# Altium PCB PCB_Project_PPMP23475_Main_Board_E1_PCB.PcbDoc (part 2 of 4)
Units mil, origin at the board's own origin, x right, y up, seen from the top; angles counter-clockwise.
Board outline 10826.77 x 2559.06 mil, 6 copper layers (Top Layer, Signal Layer 1, Signal Layer 2, Signal Layer 3, Signal Layer 4, Bottom Layer), stack 65.535 mil thick; 162 components, 91 nets, 425 pads, 676 vias.
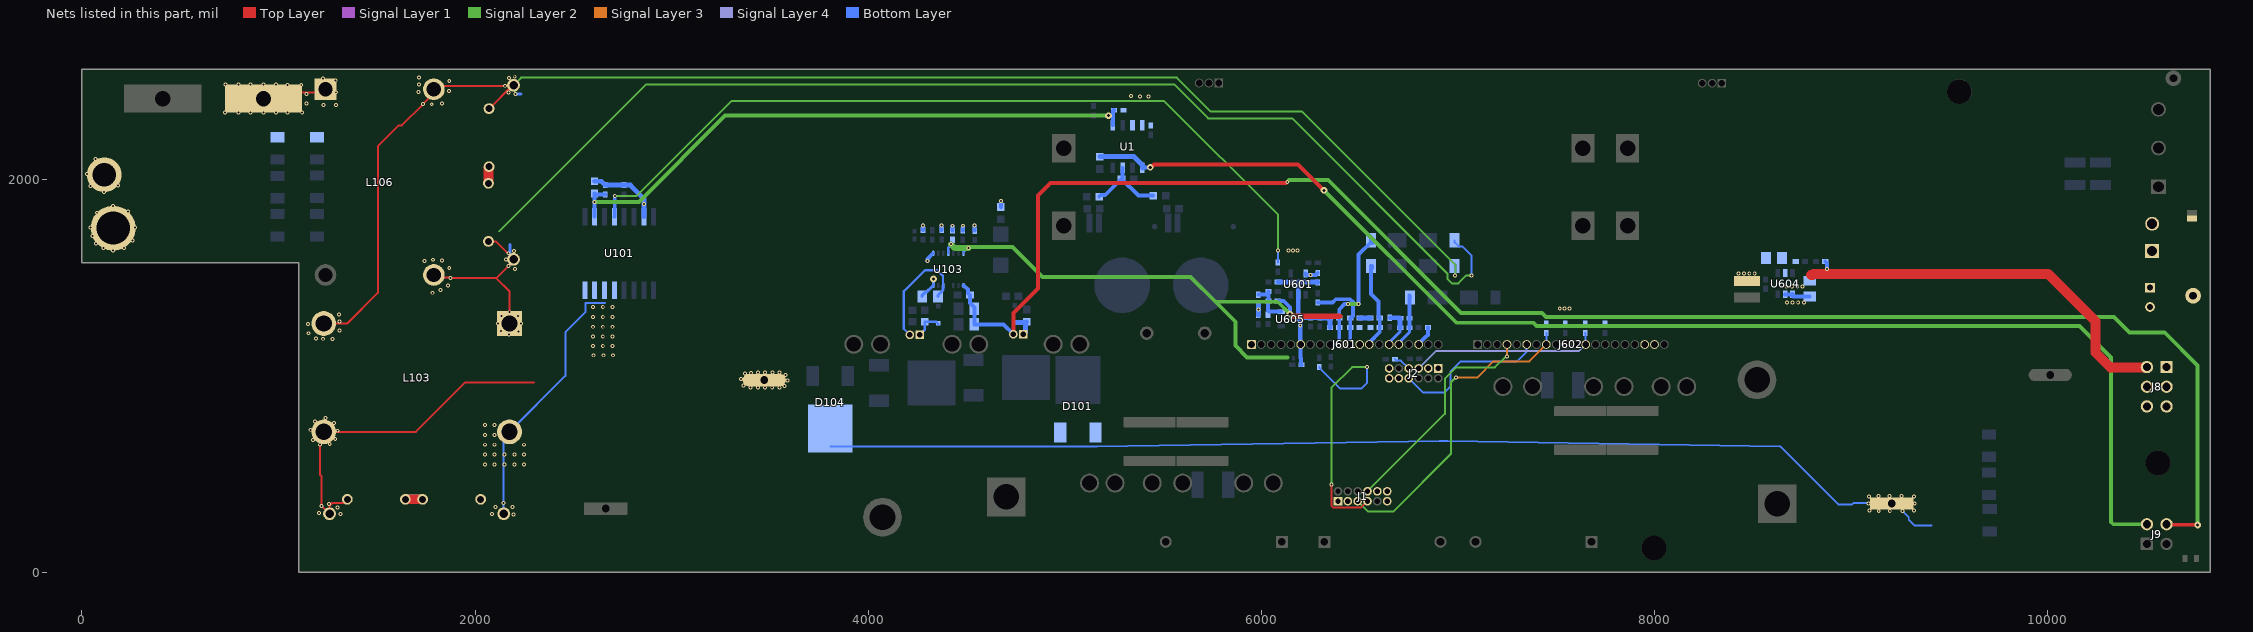
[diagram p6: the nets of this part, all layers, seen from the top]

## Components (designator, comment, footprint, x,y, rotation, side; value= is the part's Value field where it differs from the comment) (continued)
R624 "RC1206FR-071ML" 1206 9702,646 r270 bottom value=1.00Meg
R625 "CRCW040218K0FKEDC" FP-CRCW040218K0FKEDC_0402-MFG 6181,1090 r180 bottom value=18k
R626 "RC0402FR-0715KL" 0402#1 6657,1085 r180 bottom value=15.0k
R632 "CRCW04026K19FKED" 0402#1 6060,1381.49 r0 bottom value=6.19k
R637 "RC0402FR-0715KL" 0402#1 6780,1088 r180 bottom value=15.0k
R640 "RC0402FR-071KL" 0402#1 6034,1287.49 r90 bottom value=1.00k
R641 "CRCW040288K7FKED" 0402#1 8845,1582 r0 bottom value=88.7k
R642 "RC0402FR-073KL" 0402#1 5985,1286.49 r270 bottom value=3.00k
R643 "CRCW040222K1FKED" 0402#1 8742,1582 r0 bottom value=22.1k
RT1 "B59451C1130B070" S237 5564.64,1218 r180 top value=56
SW_PH1_1 "0312-0-15-15-34-27-10-0" Mill-Max_0312-0-15-15-34-27-10-0 5126,455 r90 top
SW_PH1_2 "0312-0-15-15-34-27-10-0" Mill-Max_0312-0-15-15-34-27-10-0 5256,455 r90 top
SW_PH2_1 "0312-0-15-15-34-27-10-0" Mill-Max_0312-0-15-15-34-27-10-0 8034,946 r270 top
SW_PH2_2 "0312-0-15-15-34-27-10-0" Mill-Max_0312-0-15-15-34-27-10-0 8164,946 r270 top
TP101 "Vo" Keystone5000 10640,2514 r180 top value=Red
TP103 "PGND_PFC" Keystone5001 10740,1408 r180 top value=Black
U1 "UCC5350SBDR" D0008B_HV 5320,2167 r270 bottom
U101 "ACS724KMATR-50AB-T" SOIC-16 2734,1623 r90 bottom
U103 "UCC21225ANPL" NPL0013A 4408,1542.38 r270 bottom
U601 "OPA376AIDBVR" DBV0005A_N 6188,1467.49 r90 bottom
U604 "TPS560430XDBVR" DBV0006A_N 8665,1469 r270 bottom
U605 "TLV431AIDBZR" DBZ0003A_N 6148,1289.49 r0 bottom
VB_LF_1 "0312-0-15-15-34-27-10-0" Mill-Max_0312-0-15-15-34-27-10-0 4941,1161 r270 top
VB_LF_2 "0312-0-15-15-34-27-10-0" Mill-Max_0312-0-15-15-34-27-10-0 5077,1161 r270 top
VB_PH1_1 "0312-0-15-15-34-27-10-0" Mill-Max_0312-0-15-15-34-27-10-0 5910,455 r90 top
VB_PH1_2 "0312-0-15-15-34-27-10-0" Mill-Max_0312-0-15-15-34-27-10-0 6061,455 r90 top
VB_PH2_1 "0312-0-15-15-34-27-10-0" Mill-Max_0312-0-15-15-34-27-10-0 7229,946 r270 top
VB_PH2_2 "0312-0-15-15-34-27-10-0" Mill-Max_0312-0-15-15-34-27-10-0 7380,946 r270 top

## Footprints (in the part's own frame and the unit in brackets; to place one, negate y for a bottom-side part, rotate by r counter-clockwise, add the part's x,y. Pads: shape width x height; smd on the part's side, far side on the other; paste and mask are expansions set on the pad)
0402#1 [mm] "0402 from SM-752 data"
  rect 0.8x0.6 smd: 1(-0.6,0) 2(0.6,0)
  silkscreen extent -1.22,-0.52 1.22,0.52, body extent -0.55,-0.3 0.55,0.3, height 0.6
0402#2 [mm] "Chip Capacitor, Body 1.0x0.5mm, IPC High Density"
  rect 0.6x0.5 smd: 1(-0.5,0) 2(0.5,0)
  body extent -0.55,-0.3 0.55,0.3, height 1.3
0603 [mm] "0603 from SM-752 data"
  rect 1x0.95 smd: 1(-0.8,0) 2(0.8,0)
  silkscreen extent -1.52,-0.69 1.52,0.69, body extent -0.87,-0.47 0.87,0.47, height 1
0805_HV [mil] "0805 with 30mil clearance between pads"
  rect 50x63 smd: 1(-40,0) 2(40,0)
  silkscreen extent -74,-40 74,40, body extent -43,-29 43,29, height 57
1206 [mm] "1206 from SM-752 data"
  rect 1.3x1.85 smd: 1(-1.45,0) 2(1.45,0)
  silkscreen extent -2.4,-1.21 2.4,1.21, body extent -1.7,-0.9 1.7,0.9, height 1.35
1210_220 [mm] "1210"
  rect 1.3x2.7 smd: 1(-1.45,0) 2(1.45,0)
  silkscreen extent -2.32,-1.57 2.32,1.57, body extent -1.7,-1.35 1.7,1.35, height 2.2
1812_254 [mm] "SMD, 2-Leads, Body 4.8x3.4mm"
  rect 1.6x3.4 smd: 1(-2,0) 2(2,0)
  silkscreen extent -0.8,-1.7 0.8,1.7, body extent -2.4,-1.7 2.4,1.7, height 2.54
CAPPR250W50D630H1120 [mm] "PANASONIC"
  rect 1.25x1.25 hole 0.75: 1(-1.25,0)
  round 1.25 hole 0.75: 2(1.25,0)
  silkscreen extent -3.4,-3.4 3.4,3.4, body extent -3.37,-3.39 3.4,3.39, height 12.21
D0008B_HV [mm] "SOIC, 8-Leads, Body 4.9x3.9mm, Pitch 1.27mm, HV / Isolation option"
  rrect17% 1.4x0.6 smd: 1(-2.75,1.905) 2(-2.75,0.635) 3(-2.75,-0.635) 4(-2.75,-1.905) 5(2.75,-1.905) 6(2.75,-0.635) 7(2.75,0.635) 8(2.75,1.905)
  silkscreen extent -3.3,-2.5 0.9,2.5, body extent -3,-2.45 3,2.45, height 1.63
DBV0005A_N [mm] "SOT23, 5-Leads, Body 2.9x1.6mm, Pitch 0.95mm, Lead Span 2.8mm, IPC Medium Density"
  rrect17% 1x0.6 smd: 1(-1.375,0.95) 2(-1.375,0) 3(-1.375,-0.95) 4(1.375,-0.95) 5(1.375,0.95)
  silkscreen extent -0.25,-1.55 0.25,1.55, body extent -1.42,-1.46 1.42,1.46, height 1.09
DBV0006A_N [mm] "SOT23, 6-Leads, Body 2.9x1.6mm, Pitch 0.95mm, Lead Span 2.8mm, IPC Medium Density"
  rrect17% 1x0.6 smd: 1(-1.375,0.95) 2(-1.375,0) 3(-1.375,-0.95) 4(1.375,-0.95) 5(1.375,0) 6(1.375,0.95)
  silkscreen extent -1.68,-1.55 0.5,1.55, body extent -1.42,-1.46 1.42,1.46, height 1.12
DBZ0003A_N [mm] "SOT23, 3-Leads, Body 2.9x1.3mm, Pitch 0.95mm, Lead Span 2.4mm, IPC Medium Density"
  rrect17% 1x0.6 smd: 1(-1.2,0.95) 2(-1.2,-0.95) 3(1.2,0)
  silkscreen extent 0.2,-1.5 0.7,1.5, body extent -1.26,-1.46 1.26,1.46, height 0.98
DPAK [mm] "D-PAK, 3-Pads, Body 6.22x6.73mm (max), TO-252AA using nominal STEP model"
  rrect6% 2.6x1.6 smd: 1(-3.4,2.28) 3(-3.4,-2.28)
  rrect2% 6.2x5.8 smd paste-3: 2(3.4,0)
  body extent -3.86,-3.29 5.84,3.29, height 2.48
FCC_disclaimer [mil]
FP-86H-22021C_PTH_IND_30MM0_14MM2-MFG [mm]
  rrect2% 5x5 hole 3.3 paste-2539.97 mask+0: 1(-8,-1.3)
  round 5 hole 3.3 paste-2539.97 mask+0: 2(8,1.3)
  silkscreen extent -15,-7.1 15,7.1, body extent -15.1,-7.2 15.1,7.2, height 0.25
FP-ARCDC302030E282N2B_PTH_30MM0_20MM0-MFG [mm]
  rrect3% 3.2x3.2 hole 2.1 paste-2539.97 mask+0: 1(7,-12)
  round 3.2 hole 2.1 paste-2539.97 mask+0: 2(7,12) 3(-7,12) 4(-7,-12)
  silkscreen extent -10,-15 10.72,15, body extent -10.1,-15.1 10.1,15.1, height 0.25
FP-C2225C154KDRAC7800_2225-MFG [mm]
  rrect8% 1.3x6.7 smd paste+0 mask+0: 1(-2.5,0) 2(2.5,0)
  silkscreen extent -1.48,-3.4 1.48,3.4, body extent -3.25,-3.5 3.25,3.5, height 0.25
FP-CRCW040218K0FKEDC_0402-MFG [mm]
  rrect25% 0.4x0.6 smd paste+0 mask+0: 1(-0.45,0) 2(0.45,0)
  silkscreen extent -0.55,-0.67 0.55,0.67, body extent -0.5,-0.25 0.5,0.25, height 0.35
FP-ERJ-H3G0R00V_0603-MFG [mm]
  rrect15% 0.65x0.9 smd paste+0 mask+0: 1(-0.725,0) 2(0.725,0)
  silkscreen extent 0,-0.48 0,0.48, body extent -1.15,-0.58 1.15,0.58, height 0.25
FP-IPT60R080G7XTMA1_HSOF-8-MFG [mm]
  rrect13% 0.8x2.5 smd paste-1000 mask+0: 1(-4.2,-5.35) 2(-3,-5.35)
  round 0.709 smd paste-1000 mask+0: 3-4-5-6-7-8(4.206,-4.881)
  round 7.2 smd paste-1000 mask+0: 9(0,2.7)
  Top Layer region: -2.2,-4.1 4.6,-4.1 4.6,-6.6 3.8,-6.6 3.8,-4.6 3.4,-4.6 3.4,-6.6 2.6,-6.6 2.6,-4.6 2.2,-4.6 2.2,-6.6 1.4,-6.6 1.4,-4.6 1,-4.6 1,-6.6 0.2,-6.6 0.2,-4.6 -0.2,-4.6 -0.2,-6.6 -1,-6.6 -1,-4.6 -1.4,-4.6 -1.4,-6.6 -2.2,-6.6 -2.2,-4.1
  Top Layer region: -4.85,-1.3 4.85,-1.3 4.85,2.4 4.35,2.4 4.35,5.2 5.05,5.2 5.05,6.7 -5.05,6.7 -5.05,5.2 -4.35,5.2 -4.35,2.4 -4.85,2.4
  body extent -4.95,-5.79 4.95,5.89, height 2.31
FP-M50-3000645_HDR12-MFG [mm]
  rrect9% 1.12x1.12 hole 0.7 paste-2539.97 mask+0: 1(-3.175,-0.635)
  round 1.12 hole 0.7 paste-2539.97 mask+0: 2(-3.175,0.635) 3(-1.905,-0.635) 4(-1.905,0.635) 5(-0.635,-0.635) 6(-0.635,0.635) 7(0.635,-0.635) 8(0.635,0.635) 9(1.905,-0.635) 10(1.905,0.635) 11(3.175,-0.635) 12(3.175,0.635)
  silkscreen extent -4.73,-1.63 4.16,1.63, body extent -4.26,-1.73 4.26,1.73, height 0.25
FP-M50-3030242_HDR2-MFG [mm]
  rrect9% 1.12x1.12 hole 0.7 paste-2539.97 mask+0: 1(-0.635,0)
  round 1.12 hole 0.7 paste-2539.97 mask+0: 2(0.635,0)
  silkscreen extent -2.25,-0.97 1.62,0.97, body extent -1.72,-1.07 1.72,1.07, height 0.25
FP-M52-040023V0345_HDR3-MFG [mm]
  rrect9% 1.12x1.12 hole 0.85 paste-2539.97 mask+0: 1(-1.27,0)
  round 1.12 hole 0.85 paste-2539.97 mask+0: 2(0,0) 3(1.27,0)
  silkscreen extent -2.15,-1.97 2.15,1.37, body extent -1.91,-1.25 1.91,1.25, height 6.84
FP-M52-040023V2045_HDR20-MFG [mm]
  rrect9% 1.12x1.12 hole 0.85 paste-2539.97 mask+0: 1(-12.065,0)
  round 1.12 hole 0.85 paste-2539.97 mask+0: 2(-10.795,0) 3(-9.525,0) 4(-8.255,0) 5(-6.985,0) 6(-5.715,0) 7(-4.445,0) 8(-3.175,0) 9(-1.905,0) 10(-0.635,0) 11(0.635,0) 12(1.905,0) 13(3.175,0) 14(4.445,0) 15(5.715,0) 16(6.985,0) 17(8.255,0) 18(9.525,0) 19(10.795,0) 20(12.065,0)
  silkscreen extent -12.95,-1.97 12.95,1.37, body extent -12.7,-1.25 12.7,1.25, height 6.84
FP-PAL6493.144NL_PTH_IND_36MM0_33MM0-MFG [mm]
  rrect6% 5.6x1.6 hole 1 slot 5 at 0 deg paste-2539.97 mask+0: 1(10.25,8.3)
  rrect100% 5.6x1.6 hole 1 slot 5 at 0 deg paste-2539.97 mask+0: 2(-10.25,-8.3)
  silkscreen extent -18,-16.5 18.62,16.5, body extent -18.1,-16.6 18.1,16.6, height 0.25
FP-R523I347050P3K_RADIAL-MFG [mm]
  rrect6% 1.55x1.55 hole 1 paste-2539.97 mask+0: 1(-7.5,0)
  round 1.55 hole 1 paste-2539.97 mask+0: 2(7.5,0)
  silkscreen extent -9.15,-3.85 9.15,3.85, body extent -9.25,-3.95 9.25,3.95, height 0.25
FP-SSW-102-02-G-D_HDR4-MFG [mm]
  rrect6% 1.59x1.59 hole 1.04 paste-2539.97 mask+0: 1(1.27,-1.27)
  round 1.59 hole 1.04 paste-2539.97 mask+0: 2(1.27,1.27) 3(-1.27,-1.27) 4(-1.27,1.27)
  silkscreen extent -2.92,-2.54 3.65,2.54, body extent -3.02,-2.64 3.02,2.64, height 0.25
FP-SSW-103-02-G-D_RCPT6-MFG [mm]
  rrect6% 1.59x1.59 hole 1.04 paste-2539.97 mask+0: 1(2.54,-1.27)
  round 1.59 hole 1.04 paste-2539.97 mask+0: 2(2.54,1.27) 3(0,-1.27) 4(0,1.27) 5(-2.54,-1.27) 6(-2.54,1.27)
  silkscreen extent -4.19,-3.12 4.19,2.54, body extent -4.29,-2.64 4.29,2.64, height 0.25
FP-YXS80660T_PTH_30MM0_19MM0-MFG [mm]
  rrect4% 2.8x2.8 hole 1.85 paste-2539.97 mask+0: 1(-12,-7)
  round 2.8 hole 1.85 paste-2539.97 mask+0: 2(12,-7) 3(12,7) 4(-12,7)
  silkscreen extent -15.72,-9.5 15,9.5, body extent -15.1,-9.6 15.1,9.6, height 0.25
IEC_HighVoltage_Small [mil]
  silkscreen extent -107,-88 107,97
IEC_HotSurface_Small [mil]
  silkscreen extent -107,-93 107,92
Keystone5000 [mil] "For Keystone 500x miniature loop terminals"
  round 80 hole 40: 1(0,0)
  silkscreen extent -52,-52 52,52, body extent -49,-49 49,49, height 182
Keystone5001 [mil] "For Keystone 500x miniature loop terminals"
  round 80 hole 40: 1(0,0)
  silkscreen extent -52,-52 52,52, body extent -49,-49 49,49, height 182
Mill-Max_0312-0-15-15-34-27-10-0 [mm] "Pin Receptacle, .032-.046\" .075\" Dia, Gold, TH"
  round 2.45 hole 1.905: 1(0,0)
  silkscreen extent -1.52,-1.52 1.52,1.52, body extent -1.15,-1.15 1.16,1.15, height 0.46
Net-Tie_50milWide_30milLong [mil] "50mil net tie, no solder mask opening, no solder paste"
  rect 30x50 smd paste-20 mask-20: 1(-15,0) 2(15,0)
NPL0013A [mm] "SMD, 13-Leads, Body 5x5mm, Pitch 0.65mm"
  rrect33% 0.65x0.3 smd: 1(-2.075,1.95) 2(-2.075,1.3) 3(-2.075,0.65) 4(-2.075,0) 5(-2.075,-0.65) 6(-2.075,-1.3) 7(-2.075,-1.95) 8(2.075,-1.95) 9(2.075,-1.3) 10(2.075,-0.65) 11(2.075,0.65) 12(2.075,1.3) 13(2.075,1.95)
  silkscreen extent -2.5,-2.65 2.5,2.65, body extent -2.5,-2.5 2.5,2.5, height 0.91
S237 [mm] "EPCOS"
  round 1.75 hole 1.1: 1(-3.75,0) 2(3.75,0)
  silkscreen extent -7.5,-3.5 7.5,3.5, body extent -7.47,-3.5 7.47,3.5, height 21.99
SMA [mm] "Molded Diode, 2-Leads, Body 4.3x2.6mm, IPC Medium Density, based on OnSemi component dimensions and land pattern"
  rect 2x2 smd: 1(-2,0) 2(2,0)
  silkscreen extent -3.66,-1.57 2.79,1.57, body extent -2.6,-1.3 2.6,1.3, height 2.42
SOD-323 [mm] "NXP recommended land pattern"
  rect 0.6x0.6 smd paste-0.05: 1(-1.1,0) 2(1.1,0)
  silkscreen extent -2.06,-0.86 1.53,0.86, body extent -1.3,-0.67 1.3,0.68, height 1.1
SOIC-16 [mm] "SOIC, 16-Leads, Body 10.3x7.5mm, Pitch 1.27mm"
  rrect15% 2.25x0.65 smd: 1(-4.75,4.445) 2(-4.75,3.175) 3(-4.75,1.905) 4(-4.75,0.635) 5(-4.75,-0.635) 6(-4.75,-1.905) 7(-4.75,-3.175) 8(-4.75,-4.445) 9(4.75,-4.445) 10(4.75,-3.175) 11(4.75,-1.905) 12(4.75,-0.635) 13(4.75,0.635) 14(4.75,1.905) 15(4.75,3.175) 16(4.75,4.445)
  silkscreen extent -4.87,-5.25 3.8,5.45, body extent -5.32,-5.25 5.32,5.25, height 2.64
TE_282856-3 [mm] "Receptacle, 3x1, 5mm, R/A, TH"
  rect 1.9x1.9 hole 1.4: 1(-5,0)
  round 1.9 hole 1.4: 2(0,0) 3(5,0)
  silkscreen extent -8,-5 8,5, body extent -7.5,-5 8,5, height 19
WCAP-FTXX_L26W15H25 [mm] "Film Capacitors, 26x15x25mm"
  round 1.65 hole 1.1: 1(-11.25,0) 2(11.25,0)
  silkscreen extent -13.25,-7.75 13.25,7.75, body extent -13,-7.5 13,7.5, height 30.05
WE-MAPI_3020 [mm] "SMD, 2-Leads, Body 3.2x3.2mm"
  rect 1.3x3.4 smd: 1(-1.05,0) 2(1.05,0)
  silkscreen extent -0.1,-1.6 0.1,1.6, body extent -1.6,-1.6 1.6,1.6, height 2
WEEE_Minimum [mil] "WEEElie bin"
  silkscreen extent -95,-172 99,104
Wurth_691214110002 [mm] "Receptacle, 3.5mm, 2x1, TH"
  rect 1.8x1.8 hole 1.3: 1(-1.75,0)
  round 1.8 hole 1.3: 2(1.75,0)
  silkscreen extent -3.8,-3.4 3.5,4, body extent -3.9,-3.4 3.5,4, height 8.5
Y_CAP [mm]
  round 1.4 hole 0.9: 1(-0.165,3.701) 2(-0.165,-3.799)
  silkscreen extent 0.08,-3.7 7.72,3.67, body extent -0.47,-4.1 7.73,4, height 5

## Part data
C1: library part CMP-0007150-5, "CAP, CERM, 1 uF, 35 V, +/- 10%, X5R, 0603", Cap_Case=0603, Manufacturer="Taiyo Yuden", Supplier Part Number 1=587-1437-1-ND, TempCo=X5R, Tolerance_%=10%, Value1=Unknown, Value2=35V, ValueDisplayed=1uF
C2 C3 C4 C5: library part CMP-0097403-1, "Cap Ceramic 0.15uF 1000V X7R 10% SMD 2225 125°C Embossed Plastic T/R", Digikey Part Number=399-C2225C154KDRAC7800CT-ND, Manufacturer=KEMET, Mouser Part Number=80-C2225C154KDR, Operating Temperature Range="-55°C to +125°C", TempCo=15%, Temperature Characteristic=X7R, Tolerance_%=10%, ValueDisplayed=0.15uF
C101 C102: "CAP, CERM, 0.047 µF, 630 V, +/- 10%, X7R, 1210", Cap_Case=1210, Manufacturer=MuRata, Supplier Part Number 1=490-3516-1-ND, TempCo=X7R, Tolerance_%=10, Value1=Unknown, Value2=630V, ValueDisplayed=0.047µF
C104 C105 C111 C112: library part CMP-0009609-4, "CAP, CERM, 1000 pF, X1 400 VAC/Y2 440 VAC, +/- 20%, E, TH", Cap_Case=7x5x10mm, Manufacturer=MuRata, Supplier Part Number 1="490-16237-1-ND - Cut Tape", TempCo=E, Tolerance_%=20%, Value1=Unknown, ValueDisplayed=1000pF
C106 C110 C124: library part CMP-0092709-1, "Cap Film 0.47uF 630V PP 10% Dipped 15mm 110°C Bulk", Digikey Part Number=399-R523I347050P3K-ND, Manufacturer=KEMET, Mouser Part Number=80-R523I347050P3K, Operating Temperature Range="-40°C to +110°C", Tolerance_%=10%, ValueDisplayed=0.47uF, Voltage Ac Rating X=310V
C108 C109: library part 890334026034, "WCAP-FTXX Film Capacitor, THT, L26W15H25, 2.2uF, 310V", Capacitance Tolerance=+/-10%, Insulation Resistance="10000Ohm x F", Manufacturer="Wurth Elektronik", Operating Temperature="-40 to +105degC", Rated Voltage=310VAC, Rate of Voltage Rise=170V/us
C113 C120 C623: library part CMP-0860555-1, "CAP, CERM, 0.1 µF, 25 V,+/- 10%, X7R, 0402", Cap_Case=0402, Manufacturer=Yageo, TempCo=X7R, Tolerance_%=10%, Value2=25V, ValueDisplayed=0.1µF
C114: "CAP, CERM, 1uF, 6.3V, +/-10%, X5R, 0603", Cap_Case=0603, Manufacturer=MuRata, Supplier Part Number 1=81-GRM185R60J105KE26, TempCo=X5R, Tolerance_%=10, Value1=Unknown, Value2=6.3V, ValueDisplayed=1µF
C115: "CAP, CERM, 1000pF, 6.3V, +/-10%, X5R, 0402", Cap_Case=0402, Manufacturer=MuRata, Supplier Part Number 1=GRM155R60J102KA01D-ND, TempCo=X5R, Tolerance_%=10, Value1=Unknown, Value2=6.3V, ValueDisplayed=1000pF
C116 C118 C126: library part CMP-0007827-2, "CAP, CERM, 22 uF, 16 V, +/- 20%, X5R, 0805", Cap_Case=0805, Manufacturer=TDK, Supplier Part Number 1=445-7647-1-ND, TempCo=X5R, Tolerance_%=20%, Value1=Unknown, Value2=16V, ValueDisplayed=22uF
C117: library part CMP-0081457-1, "CAP, CERM, 1 µF, 10 V,+/- 20%, X5R, 0402", Cap_Case=0402, Manufacturer="Yageo America", TempCo=X5R, Tolerance_%=20%, Value2=10V, ValueDisplayed=1µF
C119: "CAP, CERM, 1uF, 25V, +/-10%, X7R, 0603", Cap_Case=0603, Manufacturer=TDK, Supplier Part Number 1=445-5956-1-ND, TempCo=X7R, Tolerance_%=10, Value1=Unknown, Value2=25V, ValueDisplayed=1uF
C122 C123 C128: library part CMP-0006235-2, "CAP, CERM, 1000 pF, 50 V, +/- 10%, X7R, 0402", Cap_Case=0402, Manufacturer=Kemet, Supplier Part Number 1=399-1032-1-ND, TempCo=X7R, Tolerance_%=10%, Value1=Unknown, Value2=50V, ValueDisplayed=1000pF
C127: library part CMP-0860557-1, "CAP, CERM, 4700 pF, 25 V,+/- 10%, X7R, 0402", Cap_Case=0402, Manufacturer=Yageo, TempCo=X7R, Tolerance_%=10%, Value2=25V, ValueDisplayed=4700pF
C130 C131: library part CMP-0009326-2, "CAP, CERM, 0.1 uF, 1000 V, +/- 10%, X7R, 1812", Cap_Case=1812, Manufacturer=Kemet, Supplier Part Number 1=399-6523-1-ND, TempCo=X7R, Tolerance_%=10%, Value1=Unknown, Value2=1000V, ValueDisplayed=0.1uF
C601: "CAP, CERM, 0.1uF, 6.3V, +/-10%, X7R, 0402", Cap_Case=0402, Manufacturer=MuRata, Supplier Part Number 1=GRM155R70J104KA01D-ND, TempCo=X7R, Tolerance_%=10, Value1=Unknown, Value2=6.3V, ValueDisplayed=0.1uF
C603 C608 C610 C613 C615: library part CMP-0006266-2, "CAP, CERM, 0.047 uF, 10 V, +/- 10%, X5R, 0402", Cap_Case=0402, Manufacturer=TDK, Supplier Part Number 1=445-4980-1-ND, TempCo=X5R, Tolerance_%=10%, Value1=Unknown, Value2=10V, ValueDisplayed=0.047uF
C604 C605 C606 C624: library part CMP-0860558-1, "CAP, CERM, 220 pF, 50 V,+/- 10%, X7R, 0402", Cap_Case=0402, Manufacturer=Yageo, TempCo=X7R, Tolerance_%=10%, Value2=50V, ValueDisplayed=220pF
C609 C612 C614 C616: library part CMP-0006215-2, "CAP, CERM, 10 pF, 50 V, +/- 5%, C0G/NP0, 0402", Cap_Case=0402, Manufacturer="Wurth Elektronik", Supplier Part Number 1=732-7469-1-ND, TempCo=C0G/NP0, Tolerance_%=5%, Value1=Unknown, Value2=50V, ValueDisplayed=10pF
C619: library part CMP-0010333-1, "CAP, AL, 100 uF, 25 V, +/- 20%, TH", Cap_Case="Radial 6.3x11.2", Manufacturer=Panasonic, Supplier Part Number 1=P13476-ND, Tolerance_%=20%, Value1=Unknown, Value2=25V, ValueDisplayed=100uF
C620: library part CMP-0007870-2, "CAP, CERM, 4.7 uF, 25 V, +/- 10%, X7R, 0805", Cap_Case=0805, Manufacturer=TDK, Supplier Part Number 1=445-5972-1-ND, TempCo=X7R, Tolerance_%=10%, Value1=Unknown, Value2=25V, ValueDisplayed=4.7uF
C621: library part CMP-0007989-2, "CAP, CERM, 22 uF, 6.3 V, +/- 10%, X5R, 0805", Cap_Case=0805, Manufacturer="Samsung Electro-Mechanics", TempCo=X5R, Tolerance_%=10%, Value1=Unknown, Value2=6.3V, ValueDisplayed=22uF
C622: library part CMP-0081010-1, "CAP, CERM, 2.2 µF, 25 V,+/- 20%, X5R, 0402", Cap_Case=0402, Manufacturer=MuRata, Supplier Part Number 1=490-10457-1-ND, TempCo=X5R, Tolerance_%=20%, Value2=25V, ValueDisplayed=2.2µF
D101 D102 D104 D105: library part CMP-0077041-3, "Diode, Ultrafast, 600 V, 15 A, DPAK", Manufacturer=VISHAY, Value1=15A, Value2=1.15V
D103 D106: library part CMP-0028458-2, "Diode, Schottky, 30 V, 0.2 A, SOD-323", Manufacturer="Diodes Inc.", Value1=0.2A, Value2=0.7V
D107: "Diode, Ultrafast, 600V, 1A, SMA", Manufacturer="ON Semiconductor", Supplier Part Number 1=MURA160T3GOSCT-ND, Value1=1A, Value2=1.05V
J1 J2: library part CMP-0094055-1, "12 Position Receptacle Connector 0.050\" (1.27mm) Through Hole Gold", Current_A=1A, Digikey Part Number=952-1366-5-ND, Manufacturer=Harwin, Mouser Part Number=855-M50-3000645, Operating Temperature Range="-40°C to +105°C"
J01 J3: library part CMP-0097093-1, "Connector Header Through Hole 3 position 0.050\" (1.27mm)", Current_A=1A, Digikey Part Number=952-3508-ND, Manufacturer=Harwin, Mouser Part Number=855-M52-040023V0345, Operating Temperature Range="-40°C to +105°C"
J6 J7: library part CMP-0097274-1, "2 Position Receptacle Connector 0.050\" (1.27mm) Through Hole Gold", Current_A=1A, Digikey Part Number=952-3574-ND, Manufacturer=Harwin, Mouser Part Number=855-M50-3030242, Operating Temperature Range="-40°C to +105°C"
J8: library part CMP-0090625-1, "6 Position Receptacle Connector  Through Hole", Current_A=4.7A, Digikey Part Number=SAM1214-03-ND, Manufacturer=SAMTEC, Mouser Part Number=200-SSW10302GD, Operating Temperature Range="-55°C to +125°C", Voltage_V=655V
J9: library part CMP-0090624-1, "Board-To-Board Connector, Dual, SSW Series, 4 Contacts, Receptacle, 2.54 mm, Through Hole, 2 Rows", Current_A=4.7A, Digikey Part Number=SAM1214-02-ND, Manufacturer=Samtec, Mouser Part Number=200-SSW10202GD, Operating Temperature Range="-55°C to +125°C", Voltage_V=655V
J101: "Receptacle, 3x1, 5mm, R/A, TH", Color=Green, Current_A=24, Manufacturer="TE Connectivity", Supplier Part Number 1=A98356-ND, Voltage_V=300
J601 J602: library part CMP-0097094-1, "Connector Header Through Hole 20 position 0.050\" (1.27mm)", Current_A=1A, Digikey Part Number=952-3513-ND, Manufacturer=Harwin, Mouser Part Number=855-M52-040023V2045, Operating Temperature Range="-40°C to +105°C"
J604: library part CMP-0054825-2, "Terminal Block, 3.5mm, 2x1, Tin, TH", Color=Green, Current_A=10A, Manufacturer="Wurth Elektronik", Supplier Part Number 1=732-2747-ND, Voltage_V=300V
L1 L2: library part CMP-0096870-1, "Inductor, Buck/Boost, EDY35, TH", Manufacturer=Pulse, Operating Temperature Range="-40°C to +125°C", Test Frequency=100kHz, Tolerance_%=10%
L102 L104: library part CMP-0097059-1, "Inductor 16.2uH 12mOhm 30x14.2x33.3 TH", Manufacturer="Delta Electronics", Operating Temperature Range=to, Test Frequency=200kHz
L103: library part CMP-0097286-1, "Common Mode Choke 2.8mH 3.8mΩ", Manufacturer=Sunlord, Operating Temperature Range="-40°C to +105°C", Test Frequency=10kHz, Tolerance_%=25%
L106: library part CMP-0097287-1, "COMMON MODE CHOKE 1mH @ 10kHz 2.4mohm 1000VAC", Manufacturer="Yaxin Electronics", Operating Temperature Range=to, Test Frequency=10kHz
L601: library part CMP-0064157-1, "Inductor, Shielded, 10 uH, 1.2 A, 0.322 ohm, SMD", Manufacturer="Wurth Elektronik", Supplier Part Number 1=732-5700-1-ND, Value1="0.322 ohm", Value2=1.2A, ValueDisplayed=10uH
LOGO601: library part CMP-0074837-1, "IEC 61010-1 Hot Surface Warning"
LOGO602: library part CMP-0074835-1, "IEC 61010-1 High Voltage Warning"
Logo603: library part CMP-0074847-1, "FCC_disclaimer"
Logo604: library part CMP-0074769-1
N_LF_1 N_LF_2 PGND_LF_1 PGND_LF_2 PGND_PH1_1 PGND_PH1_2 PGND_PH2_1 PGND_PH2_2 SW_PH1_1 SW_PH1_2 SW_PH2_1 SW_PH2_2 VB_LF_1 VB_LF_2 VB_PH1_1 VB_PH1_2 VB_PH2_1 VB_PH2_2: library part CMP-0055026-1, "Pin Receptacle, .032-.046\" .075\" Dia, Gold, TH", Manufacturer=Mill-Max, Supplier Part Number 1=0312-015153427100-ND
NT1: library part CMP-0078142-6, "Single point connection between nets.", Manufacturer=N/A
Q101 Q106: library part CMP-0086487-1, "MOSFET N-CH 650V 23A HSOF-8", Manufacturer=Infineon
R1: library part CMP-0097467-1, "0 Ohms Jumper 0.125W, 1/8W Chip Resistor 0603 (1608 Metric) Automotive AEC-Q200 Thick Film", Digikey Part Number=10-ERJ-H3G0R00VCT-ND, Manufacturer=Panasonic, Mouser Part Number=667-ERJ-H3G0R00V, Operating Temperature Range="-55°C to +175°C", Power_W=125mW
R101 R104: library part CMP-0022900-4, "RES, 1.00, 1%, 0.1 W, 0603", Manufacturer=Yageo, Power_W=100mW, Supplier Part Number 1=311-1.00HRCT-ND, TempCo="200 ppm/C", Tolerance_%=1%, Value2=0.1W, Value_Code=1R00, ValueDisplayed=1.00
R102 R111: library part CMP-0022751-4, "RES, 10.0, 1%, 0.1 W, 0603", Manufacturer=Yageo, Power_W=100mW, Supplier Part Number 1=311-10.0HRCT-ND, TempCo="100 ppm/C", Tolerance_%=1%, Value2=0.1W, Value_Code=10R0, ValueDisplayed=10.0
R103 R106: library part CMP-0022746-5, "RES, 10.0 k, 1%, 0.1 W, 0603", Manufacturer=Yageo, Power_W=100mW, Supplier Part Number 1=311-10.0KHRCT-ND, TempCo="100 ppm/C", Tolerance_%=1%, Value2=0.1W, Value_Code=10k0, ValueDisplayed=10.0k
R105 R114: library part CMP-0022895-5, "RES, 1.00 k, 1%, 0.1 W, 0603", Manufacturer=Yageo, Power_W=100mW, Supplier Part Number 1=311-1.00KHRCT-ND, TempCo="100 ppm/C", Tolerance_%=1%, Value2=0.1W, Value_Code=1k00, ValueDisplayed=1.00k
R107 R108 R109 R110 R112 R113: library part CMP-0017836-2, "RES, 100 k, 1%, 0.25 W, 1206", Manufacturer="Yageo America", Power_W=250mW, Supplier Part Number 1=311-100KFRCT-ND, TempCo="100 ppm/C", Tolerance_%=1%, Value2=0.25W, Value_Code=100k
R117: library part CMP-0022908-4, "RES, 20.0, 1%, 0.1 W, 0603", Manufacturer=Yageo, Power_W=100mW, Supplier Part Number 1=311-20.0HRCT-ND, TempCo="100 ppm/C", Tolerance_%=1%, Value2=0.1W, Value_Code=20R0, ValueDisplayed=20.0
R118 R120 R122: "RES, 1.0k ohm, 5%, 0.063W, 0402", Manufacturer=Vishay-Dale, Power_W=0.063, Supplier Part Number 1=541-1.0KJCT-ND, TempCo="200 ppm/C", Tolerance_%=5, Value1=5%, Value2=0.063W, Value_Code=1k00
R119: library part CMP-0023206-5, "RES, 5.11, 1%, 0.1 W, 0603", Manufacturer=Yageo, Power_W=100mW, Supplier Part Number 1=311-5.11HRCT-ND, TempCo="200 ppm/C", Tolerance_%=1%, Value2=0.1W, Value_Code=5R11, ValueDisplayed=5.11
R121: library part CMP-0026727-1, "RES, 1.00 M, 1%, 0.063 W, 0402", Manufacturer="Yageo America", Power_W=63mW, Supplier Part Number 1=311-1.00MLRCT-ND, TempCo="100 ppm/C", Tolerance_%=1%, Value2=0.063W, Value_Code=1M00, ValueDisplayed=1.00M
R601: library part CMP-0026408-2, "RES, 4.3 k, 1%, 0.063 W, 0402", Manufacturer=Yageo, Power_W=63mW, Supplier Part Number 1=541-4.32KLCT-ND, TempCo=50ppm/C, Tolerance_%=1%, Value2=0.063W, Value_Code=4k3, ValueDisplayed=4.3k
R602 R603 R604 R606 R607 R608 R612 R613 R614 R621 R622 R624: library part CMP-0018027-2, "RES, 1.00 M, 1%, 0.25 W, 1206", Manufacturer="Yageo America", Power_W=250mW, Supplier Part Number 1=311-1.00MFRCT-ND, TempCo="100 ppm/C", Tolerance_%=1%, Value2=0.25W, Value_Code=1M00, ValueDisplayed=1.00M
R609: library part CMP-0026463-2, "RES, 5.11 k, 1%, 0.063 W, AEC-Q200 Grade 0, 0402", Manufacturer=Vishay-Dale, Power_W=63mW, Supplier Part Number 1=541-5.11KLCT-ND, TempCo="100 ppm/C", Tolerance_%=1%, Value2=0.063W, Value_Code=5k11, ValueDisplayed=5.11k
R610: library part CMP-0025958-3, "RES, 10.0 k, 1%, 0.063 W, AEC-Q200 Grade 0, 0402", Manufacturer=Vishay-Dale, Power_W=63mW, Supplier Part Number 1=541-10.0KLCT-ND, TempCo="100 ppm/C", Tolerance_%=1%, Value2=0.063W, Value_Code=10k0, ValueDisplayed=10.0k
R611: library part CMP-0026722-1, "RES, 100, 1%, 0.063 W, 0402", Manufacturer="Yageo America", Power_W=63mW, Supplier Part Number 1=311-100LRCT-ND, TempCo="100 ppm/C", Tolerance_%=1%, Value2=0.063W, Value_Code=100R, ValueDisplayed=100
R615: library part CMP-0026781-1, "RES, 4.87 k, 0.1%, 0.062 W, AEC-Q200 Grade 0, 0402", Manufacturer=Panasonic, Power_W=62mW, Supplier Part Number 1=P4.87KDCCT-ND, TempCo="25 ppm/C", Tolerance_%=0.1%, Value2=0.062W, Value_Code=4k87, ValueDisplayed=4.87k
R616: library part CMP-0026822-3, "RES, 0, 5%, 0.063 W, AEC-Q200 Grade 0, 0402", Manufacturer=Vishay-Dale, Power_W=63mW, Supplier Part Number 1=541-0.0JCT-ND, TempCo="200 ppm/C", Tolerance_%=5%, Value2=0.063W, Value_Code=0000, ValueDisplayed=0
R617 R618 R619: library part CMP-0026058-3, "RES, 18.0 k, 1%, 0.063 W, AEC-Q200 Grade 0, 0402", Manufacturer=Vishay-Dale, Power_W=63mW, Supplier Part Number 1=541-18.0KLCT-ND, TempCo="100 ppm/C", Tolerance_%=1%, Value2=0.063W, Value_Code=18k0, ValueDisplayed=18.0k
R620 R623 R626 R637: library part CMP-0078583-1, "RES, 15.0 k, 1%, 0.063 W, 0402", Manufacturer="Yageo America", Power_W=63mW, Supplier Part Number 1=311-15.0KLRCT-ND, TempCo="100 ppm/C", Tolerance_%=1%, Value2=0.063W, Value_Code=15k0, ValueDisplayed=15.0k
R625: library part CMP-0094741-1, "Res Thick Film 0402 18K Ohm 1% 1/16W ±100ppm/°C Molded SMD Paper T/R", Digikey Part Number=541-4757-1-ND, Manufacturer=Vishay, Mouser Part Number=71-CRCW040218K0FKEDC, Operating Temperature Range="-55°C to +155°C", Power_W=63mW, TempCo=100ppm/°C, Tolerance_%=1%
R632: library part CMP-0026513-2, "RES, 6.19 k, 1%, 0.063 W, AEC-Q200 Grade 0, 0402", Manufacturer=Vishay-Dale, Power_W=63mW, Supplier Part Number 1=541-6.19KLCT-ND, TempCo="100 ppm/C", Tolerance_%=1%, Value2=0.063W, Value_Code=6k19, ValueDisplayed=6.19k
R640: library part CMP-0026725-1, "RES, 1.00 k, 1%, 0.0625 W, 0402", Manufacturer="Yageo America", Power_W=62.5mW, Supplier Part Number 1=311-1.00KLRCT-ND, TempCo="100 ppm/C", Tolerance_%=1%, Value2=0.0625W, Value_Code=1k00, ValueDisplayed=1.00k
R641: library part CMP-0026586-2, "RES, 88.7 k, 1%, 0.063 W, AEC-Q200 Grade 0, 0402", Manufacturer=Vishay-Dale, Power_W=63mW, Supplier Part Number 1=541-88.7KLCT-ND, TempCo="100 ppm/C", Tolerance_%=1%, Value2=0.063W, Value_Code=88k7, ValueDisplayed=88.7k
R642: library part CMP-0026733-1, "RES, 3.00 k, 1%, 0.0625 W, 0402", Manufacturer="Yageo America", Power_W=62.5mW, Supplier Part Number 1=311-3KLRCT-ND, TempCo="100 ppm/C", Tolerance_%=1%, Value2=0.0625W, Value_Code=3k00, ValueDisplayed=3.00k
R643: library part CMP-0026178-2, "RES, 22.1 k, 1%, 0.063 W, AEC-Q200 Grade 0, 0402", Manufacturer=Vishay-Dale, Power_W=63mW, Supplier Part Number 1=541-22.1KLCT-ND, TempCo="100 ppm/C", Tolerance_%=1%, Value2=0.063W, Value_Code=22k1, ValueDisplayed=22.1k
RT1: library part CMP-0002554-2, "Thermistor NTC, 4.70 ohm, 20%, 15x7mm", Manufacturer=TDK, Power_W=3.1W, Supplier Part Number 1=495-2099-ND, Tolerance_%=20%
TP101: library part 5000, "Test Point, Miniature, Red, TH", Manufacturer=Keystone, Supplier Part Number 1=36-5000-ND
TP103: library part 5001, "Test Point, Miniature, Black, TH", Manufacturer=Keystone, Supplier Part Number 1=36-5001-ND
U1: library part CMP-0077706-1, "3-kVRMS Single-Channel Isolated Gate Drivers, D0008B (SOIC-8)", Alternate Manufacturer="Texas Instruments", Alternate PartNumber=UCC5350SBD
U101: library part CMP-0077522-2, "High Accuracy, Hall-Effect Based Current Sensor, SOIC-16", Manufacturer="Allegro Microsystems Inc"
U103: library part CMP-0013548-2, "4A/6A Isolated Dual-Channel Gate Driver, NPL0013A (VLGA-13)", Alternate Manufacturer="Texas Instruments"
U601: library part CMP-0041017-1, "Precision, Low Noise, Low Iq Operational Amplifier, 2.2 to 5.5 V, -40 to 125 degC, 5-pin SOT23 (DBV5), Green (RoHS & no Sb/Br)", Manufacturer="Texas Instruments", Total Supply Voltage(Max)(+5V is 5, +/-5V is 10)=5.5, Total Supply Voltage(Min)(+5V is 5, +/-5V is 10)=2.2
U604: library part CMP-0065097-3, "4V to 36 V 0.6 A Synchronous Step-Down Converter, DBV0006A (SOT-23-6)", Alternate Manufacturer="Texas Instruments", Alternate PartNumber=TPS560430XDBVT
U605: library part CMP-0033044-1, "Low Voltage Adjustable Precision Shunt Regulator, 39 ppm / degC, 15 mA, -40 to 85 degC, 3-pin SOT-23 (DBZ), Green (RoHS & no Sb/Br)", Manufacturer="Texas Instruments", Rating=Catalog, Temp Coeff(Max)(ppm/ degree C)=129, Temp Coeff(Typ)(ppm/ degree C)=39

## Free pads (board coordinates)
  round 177.17 hole 118.11: 1(114,2023)
  round 228.35 hole 169.29: 1(159.52,1752)
  rect 393.7x141.73 hole 78.74 square: 1(924,2411) 2(412.19,2411)
  rect 118.11x145.67 hole 78.74 square: 1(4994.89,1763.91) 1(4994.89,2157.61) 1(7635.89,1764.3) 1(7635.89,2158) 1(7863.11,1764.3) 1(7863.11,2158)
  round 125.98 hole 125.98: 1(7997,124) 1(9551,2446) 1(10562,557)

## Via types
v1: diameter 20, hole 10, Top Layer to Bottom Layer, 563 vias
v2: diameter 20, hole 10, Top Layer to Bottom Layer, tented both sides, 103 vias
v3: diameter 34, hole 16, Top Layer to Bottom Layer, 10 vias

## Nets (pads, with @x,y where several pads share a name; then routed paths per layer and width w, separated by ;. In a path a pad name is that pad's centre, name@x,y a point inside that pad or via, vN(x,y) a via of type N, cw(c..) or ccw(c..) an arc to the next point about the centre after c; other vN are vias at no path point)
5VP: C113.1 C114.1 C117.1 C120.1 C601.2 C621.1 J1.3 J2.3 J8.2 J602.19 L601.2 R632.2 R641.2 U1.1 U101.10 U103.4 U103.7 U601.5 | length 8032.6
  Top Layer w30: v3@6158.08,1303.49 6398.57,1303.49 ; J602.19@8000,1159 J602.19@8000,1159.97 J602.19@8000,1162.07
  Top Layer w50: 8796,1513 8804,1513 8809,1518 10003,1518 10243,1278 10243,1119 10319.49,1042.51 J8.2@10505,1042.51
  Signal Layer 2 w20: v2(2608,1885) 2833.64,1885 3272.64,2324 v3(5223,2324) ; v1(4511,1650) 4517,1656 4734,1656 4887,1503 5640.66,1503 5766.33,1377.33 ; 6133.75,1094 5928,1094 5868,1154 5868,1275.66 5766.33,1377.33 ; v3(6146,1314.49) 6146,1315 6083.67,1377.33 5766.33,1377.33
  Signal Layer 2 w30: v1(4421,1670) 4441,1650 v1(4511,1650)
  Signal Layer 3 w20: J602.19@8000,1158.56 J602.19@8000,1159
  Bottom Layer w12: U103.4@4408,1624.07 4408,1652.81 4421,1665.81 v1(4421,1670) ; U103.7@4484.77,1624.07 4484.77,1630.77 4499.79,1645.79
  Bottom Layer w20: U101.10@2609,1810.01 2608,1811.01 v2(2608,1885) C114.1@2608,1927.5 2612.13,1923.38 C113.1@2663,1923.38 ; v1(4511,1650) v1@4513.68,1652.68 ; U1.1@5245,2275.27 5245,2324 ; 5245,2330.35 5245,2349.94 5247.06,2352 C120.1@5251,2352 ; R632.2@6083.62,1381.49 6114,1381.49 6146,1349.49 v3(6146,1314.49) ; U601.5@6225.4,1521.62 6225.4,1515.3 6227.21,1513.49 v1(6249.44,1513.49) 6277.38,1513.49 C601.2@6287,1523.11 ; R641.2@8868.62,1582 8878,1572.62 v2(8878,1545)
  other v2: 8426.77,1522 8454.51,1522 8482.26,1522 8510,1522
12V_inrush: C1.1 J9.3 U1.5 | length 6614.5
  Top Layer w20: v3(5435,2061) 5438.72,2061 5453.72,2076 6187,2076 v3(6319,1944)
  Signal Layer 2 w20: v3(6319,1944) 6992.5,1270.5 7383.79,1270.5 7400.29,1254 10162,1254 10322,1094 10322,257.22 10333.72,245.5 J9.3@10505,245.5
  Bottom Layer w20: U1.5@5395,2058.73 5396.13,2059.87 5433.87,2059.87 v3(5435,2061)
  Bottom Layer w25: C1.1@5178,2115.5 5352.61,2115.5 5395,2073.1 U1.5@5395,2058.73
12VP: C126.1 C619.1 C620.1 J1.1 J2.1 J8.4 J8.6 J604.1 R117.2 U103.13 U604.4 U604.5 | length 289.5
  Signal Layer 2 w20: J604.1@10517.9,1636.2 J604.1@10532,1636.2
  Signal Layer 3 w20: v1(4675,1889.02) v1@4675,1890.91
  Bottom Layer w15: C126.1@4275,1404 4275,1410.5 4292.5,1428 4298.54,1428 4325.93,1455.39 4329.63,1455.39 4331.23,1456.98 U103.13@4331.23,1460.69 4331.61,1461.07 4331.61,1492.61 v3(4332,1493)
  Bottom Layer w20: R117.2@4675,1859.5 v1(4675,1889.02) ; U604.5@8665,1414.87 U604.4@8702.4,1414.87 ; U604.4@8707.27,1404 C620.1@8789,1404
  Bottom Layer w25: U604.4@8702.4,1408.37 U604.4@8702.4,1414.87
  other v1: 8674,1374 8702.67,1374 8731.33,1374 8760,1374
  other v2: 7518.22,1342.17 7542.72,1342.17 7567.22,1342.17 6137.32,1639 6160.16,1639 6183,1639
+BRDG_N: D103.2 J6.1 R105.1 | length 127.7
  Bottom Layer w25: D103.2@4745,1271.69 R105.1@4802.19,1271.69 ; J6.1@4789,1212 4799.8,1222.8 4799.8,1269.3 R105.1@4802.19,1271.69 ; R105.1@4806,1275.5 R105.1@4802.19,1271.69
+BRDG_P: D106.2 J7.1 R114.1 | length 152.7
  Bottom Layer w12: J7.1@4262,1209 4288.5,1235.5 R114.1@4288.5,1275 4345.69,1275 D106.2@4357,1263.69 ; J7.1@4269.19,1199.88 J7.1@4271,1201.69
-BRDG_N: C116.2 C118.2 C119.1 J6.2 J9.4 U103.8 | length 8492.7
  Top Layer w20: J6.2@4739,1212 4739,1320 4864,1445 4864,1917 4928,1981 6126,1981 v1(6132,1987) ; J9.4@10605,245.5 10607.5,243 10762,243 v3(10763,242)
  Signal Layer 2 w20: v1(6132,1987) 6141,1996 6340.54,1996 7016.54,1320 7428,1320 7449,1299 10338,1299 10416,1221 10596,1221 10763,1054 v3(10763,242)
  Bottom Layer w20: U103.8@4484.77,1460.69 4486.07,1460.69 4507.81,1438.94 4507.81,1420.7 4516.51,1412 C119.1@4517.5,1412 4517.5,1370 4540,1347.5 C116.2@4540,1341 C118.2@4540,1262 4689,1262 J6.2@4739,1212
-BRDG_P: C126.2 J7.2 U103.11 | length 602.3
  Bottom Layer w12: J7.2@4212,1209 4181,1240 4181,1430.07 4288.93,1538 4350.64,1538 4380.81,1507.82 U103.11@4380.81,1462.28
  Bottom Layer w15: C126.2@4355,1404 4355,1410.5 4380.81,1436.31 U103.11@4380.81,1459.09
AC_CUR_G: C603.1 J601.11 R611.1 R615.2 | length 417.5
  Bottom Layer w20: R611.1@6287,1372.87 6361.52,1372.87 6378.65,1390 6451.36,1390 6466,1375.36 6466,1304.17 6456.31,1294.49 C603.1@6452.38,1294.49 R615.2@6452.38,1246.49 6452.38,1161.38 J601.11@6450,1159
AC_CUR_SENSE: R609.1 U101.12 | length 4162
  Signal Layer 2 w10: v2(2711,1915) 2821,1915 3304,2398 5506,2398 6085,1819 v2(6085,1638)
  Bottom Layer w10: R609.1@6084,1577.11 6084.5,1577.61 6084.5,1637.5 v2(6085,1638)
  Bottom Layer w20: U101.12@2709,1810.01 2711,1812.01 v2(2711,1915)
AC_L: C104.1 C108.2 L103.2 L106.4 R603.2 | length 7453.7
  Top Layer w10: L103.2@1230.56,1266.59 1350.59,1266.59 1506,1422 1506,2167.85 1612.62,2274.47 1627.47,2274.47 v1(1736,2383) 1736,2385.71 1813.06,2462.77 1813.06,2474.91 C108.2@2186.71,2474.91 ; C104.1@2071.51,2359.72 C108.2@2186.71,2474.91 ; C108.2@2200,2474.91 C108.2@2186.71,2474.91
  Signal Layer 2 w10: v1(2206,2435) 2204.09,2436.91 2204.09,2487 2235.09,2518 5570.5,2518 5743.5,2345 6208,2345 6987,1566 6987,1512 v1(6986,1511)
  Bottom Layer w10: R603.2@6983.09,1559 6986,1556.09 v1(6986,1511)
  Bottom Layer w15: v1(2206,2435) 2206.96,2434.04 2233.3,2434.04
  other v1: 1275,1188 1227,1189 1191,1190 1152,1217 1310,1231 1151,1265 1310,1276 1308,1312 1780,2382 1831,2385 2171,2442 1712,2445 1867,2449 2153,2476 1715,2483 1869,2500 2172,2516 1715,2519 2202,2522
AC_L1: C105.2 C109.2 D101.1 D101.3 D104.2 L1.2 L2.1 L103.3 | length 7545.4
  Top Layer w10: C105.2@1351.44,352.49 1273.49,352.49 1260.09,339.09 C109.2@1260.09,299 1259.54,299 1220.54,338 1220.54,338.54 1220,339.09 1220,489.5 1211,498.5 v1(1211,650) 1212.91,651.91 1212.91,697.76 L103.3@1230.56,715.41 1699.41,715.41 1951,967 2301,967
  Bottom Layer w10: D104.2@3807.24,641 5163.41,641 6906.92,669.99 cw(c6908,605) 6909.18,669.99 6909.25,669.99 6915.21,669.99 6944.98,670 cw(c6945,605) 6946.22,669.99 8641,641 8643.93,638.07 8935,347 9005.15,347 9011.15,353 9087,353 v1(9088,352) 9234.73,352 9261,325.73 v1(9261,313) 9293.49,280.51 9293.49,268.51 9323.07,238.93 9409.31,238.93
  other v1: 1315,297 1207,302 9141,312 9197,313 9094,315 9321,316 1300,330 1220,338 1258,348 9324,352 9092,386 9320,386 9195,389 9257,389 9140,390 1261,653 1175,675 1289,679 1300,721 1164,726 1283,761 1186,768 1239,785 3476,940 3512,940 3548,940 3440,941 3402,942 3574,948 3366,952 3589,977 3354,984 3579,1004 3374,1012 3405,1016 3440,1017 3476,1017 3513,1017 3548,1017
AC_N: C108.1 C111.2 L103.1 L106.3 R604.2 | length 6966.8
  Top Layer w10: L106.3@1782.03,1499 1783.94,1500.91 1874.09,1500.91 v1(1876,1499) 1877.44,1497.56 2108.47,1497.56 ; C111.2@2068.51,1684.44 2104.65,1684.44 C108.1@2196,1593.09 2200,1589.09 v1(2169.91,1559) 2108.47,1497.56 ; v1(2175,1324) 2175,1267.03 L103.1@2175.44,1266.59 2175.44,1430.59 2108.47,1497.56
  Signal Layer 2 w10: 2123,1736 2870,2483 5556,2483 5729,2310 6157,2310 6946,1521 6946,1494.43 6969.43,1471 7002.57,1471 7042.57,1511 v1(7069,1511)
  Bottom Layer w10: R604.2@6983.09,1690 6983.09,1679.17 7003.68,1658.58 7023.29,1658.58 7069,1612.88 v1(7069,1511)
  Bottom Layer w15: 2177,1668.25 2177,1612.09 C108.1@2196,1593.09 C108.1@2200,1589.09
  other v1: 2174,1210 2222,1226 2133,1228 2118,1266 2234,1266 2219,1305 2135,1306 1784,1423 1824,1437 1862,1460 2203,1545 1869,1550 1742,1585 1831,1587 1786,1591 2157,1593 2170,1624 2199,1636
AC_N1: C109.1 C112.1 L103.4 U101.5 U101.6 U101.7 U101.8 | length 1342.9
  Bottom Layer w10: C109.1@2145.91,299 2145.91,685.88 L103.4@2175.44,715.41 2460,999.97 2460,1223 2561,1324 2561,1369.99 2611,1369.99 2661,1369.99
  other v1: 2196,296 2087,297 2104,334 2190,334 2146,354 2050,550 2100,550 2150,550 2200,550 2250,550 2050,600 2100,600 2150,600 2200,600 2250,600 2050,650 2100,650 2250,650 2050,700 2100,700 2050,750 2100,750
  other v2: 2603,1105 2653,1105 2703,1105 2600,1152 2650,1152 2700,1152 2600,1200 2650,1200 2700,1200 2600,1250 2650,1250 2700,1250 2600,1300 2650,1300 2700,1300 2600,1350 2650,1350 2700,1350
ACL_SENSE: C605.1 J601.13 R613.1 R618.2 | length 453.9
  Bottom Layer w20: J601.13@6550,1159 6550,1171 6602.62,1223.62 C605.1@6602.62,1246.49 R618.2@6602.62,1294.49 6598.69,1294.49 6596.87,1296.3 6596.87,1377.65 6556.91,1417.61 R613.1@6556.91,1559 ; R613.1@6563.4,1548.17 R613.1@6563.4,1559
ACN_SENSE: C606.1 J601.10 R614.1 R619.2 | length 652.2
  Signal Layer 2 w20: v1(6441,1365) v1(6494,1365)
  Bottom Layer w20: J601.10@6400,1159 6396.62,1162.38 C606.1@6396.62,1246.49 R619.2@6396.62,1294.49 6396.62,1338.67 6422.96,1365 v1(6441,1365) ; v1(6494,1365) 6494,1617.26 6556.91,1680.17 R614.1@6556.91,1691 ; R614.1@6565.49,1676.17 R614.1@6565.49,1687
ADC_SENSE: J601.1
AGND: C113.2 C114.2 C115.2 C117.2 C120.2 C122.2 C123.2 C127.2 C128.2 C601.1 C603.2 C604.2 C605.2 C606.2 C608.2 C609.2 C610.2 C612.2 C613.2 C614.2 C615.2 C616.2 C619.2 C620.2 C621.2 C622.2 C624.1 J1.10 J1.11 J1.12 J2.10 J2.11 J2.12 J8.1 J8.3 J8.5 J601.6 J601.12 J601.15 J601.18 J602.18 J604.2 NT1.2 R121.1 R610.2 R615.1 R617.1 R618.1 R619.1 R625.1 R642.1 R643.1 TP103.1 U1.3 U1.4 U101.15 U103.1 U601.2 U604.2 U605.3 | length 1828.4
  Bottom Layer w15: J601.15@6650,1159 6650,1169 6706.38,1225.38 R617.1@6706.38,1244.49
  Bottom Layer w20: C122.2@4279,1741.62 v1(4279,1766) ; v1(4301,1585) 4301,1595.14 4329.93,1624.07 U103.1@4331.23,1624.07 ; C123.2@4374,1741.62 v1(4374,1766) ; C117.2@4429,1739.62 v1(4429,1764) ; C127.2@4482,1739.62 v1(4482,1764) ; R121.1@4542,1738.62 v1(4542,1764.21) ; J601.6@6200,1159.97 6199.36,1159.33 6199.36,1090.64 R625.1@6198.72,1090 6199.03,1090 6200.84,1088.19 6200.84,1057.81 6202.65,1056 C624.1@6204.62,1056 ; J601.18@6800,1159.97 6800,1162.37 6834.65,1197.02 6835.91,1197.02 6847.62,1208.74 C615.2@6847.62,1246
  Bottom Layer w25: C114.2@2608,1990.5 2643.13,1990.5 C113.2@2663,1970.62 C115.2@2758,1970.62 2790.38,1970.62 2859,1902 U101.15@2859,1810.01 ; R642.1@5985,1310.11 C622.2@5985,1365.87 ; R610.2@6083.62,1477.49 6188,1477.49 ; J601.6@6200,1159 6199.51,1159.49 6198,1161 v2(6198,1257.49) U605.3@6198,1292.24 ; C601.1@6287,1475.87 6285.38,1477.49 6188,1477.49 ; C606.2@6349.38,1246.49 R619.1@6349.38,1294.49 6301.62,1294.49 C610.2@6298,1298.11 C608.2@6250,1298.11 6203.87,1298.11 U605.3@6198,1292.24 ; C603.2@6499.62,1294.49 R618.1@6555.38,1294.49 ; C613.2@6654,1296.11 6702.76,1296.11 C604.2@6706.38,1292.49 R617.1@6706.38,1244.49 ; 6188,1477.49 U601.2@6188,1413.35 6188,1296.73 U605.3@6195.24,1289.49 U605.3@6198,1292.24
  other v1: 5382,2422 5427,2422 5337,2423
  other v2: 5985,1337.99 8671,1455 8698.67,1455 8726.33,1455 8754,1455 2859,1875
CUR_REF: C622.1 R616.2 R632.1 R640.2 U605.2 | length 218.9
  Bottom Layer w20: C622.1@5985,1413.11 6035.76,1413.11 ; R616.2@6036.38,1429.49 6035.76,1428.87 6035.76,1413.11 ; U605.2@6100.76,1326.89 6038.6,1326.89 6034,1331.49 6034,1379.11 R632.1@6036.38,1381.49 6036.38,1412.49 6035.76,1413.11
DC_SENSE: C604.1 J601.16 R612.1 R617.2 | length 278.1
  Bottom Layer w15: J601.16@6700,1159 6700,1169 6753.62,1222.62 R617.2@6753.62,1244.49
  Bottom Layer w20: R612.1@6753.29,1395.38 R612.1@6756.91,1399 ; R617.2@6753.62,1244.49 C604.1@6753.62,1292.49 R612.1@6753.62,1409.78
DRV_Relay: R101.1 R104.1 R119.1 U1.7 | length 407.9
  Bottom Layer w10: R101.1@5175.5,1912 R101.1@5176.48,1912 ; R104.1@5449.52,1917 R104.1@5450.5,1917
  Bottom Layer w20: R101.1@5175.5,1912 5184.2,1920.7 5206.22,1920.7 5287.52,2002 R119.1@5288.5,2002 ; U1.7@5295,2058.73 5293.19,2056.92 5293.19,2006.69 R119.1@5288.5,2002 ; R104.1@5449.52,1917 5374.49,1917 5289.49,2002 R119.1@5288.5,2002
EARTH: C104.2 C105.1 C111.1 C112.2 pad.1@114,2023 pad.1@159.52,1752 | length 611.3
  Top Layer w50: C105.1@1645.72,372.49 C112.2@1732.44,372.49 ; C111.1@2068.51,1979.72 2068.51,2061.44 C104.2@2071.51,2064.44
  Signal Layer 1 w50: C105.1@1645.72,372.49 C112.2@1733.44,372.49
  Signal Layer 2 w50: C105.1@1645.72,372.49 C112.2@1733.44,372.49
  Signal Layer 3 w50: C105.1@1645.72,372.49 C112.2@1733.44,372.49
  Signal Layer 4 w50: C105.1@1645.72,372.49 C112.2@1733.44,372.49
  Bottom Layer w50: C105.1@1645.72,372.49 C112.2@1733.44,372.49
  other v2: 158,1638 111,1650 215,1651 73,1674 257,1689 53,1711 45,1755 270,1756 77,1830 235,1836 159,1865 113,1935 44,1966 184,1968 25,2027 70,2103
GaN_F1: J1.8 J602.4 | length 1161
  Signal Layer 1 w10: J602.4@7249.49,1159.46 J602.4@7250,1159.97
  Signal Layer 2 w10: J1.8@6540,413 6934,807 6934,985.5 6991.5,1043 7187.93,1043 7241.02,1096.09 7248.09,1096.09 v1(7250,1098)
  Signal Layer 3 w10: v1(7250,1098) J602.4@7250,1159.97
GaN_F2: J2.8 J602.6 | length 798.5
  Bottom Layer w10: J2.8@6750,988 6823,915 6931.71,915 6963.5,946.78 6963.5,1022.78 7014.72,1074 7302,1074 7350,1122 J602.6@7350,1159.97
HS_TEMP1: J1.7 R620.1 | length 1406.3
  Top Layer w10: v1(6356.71,446.76) 6357.95,445.52 6357.95,337.97 6364.97,330.95 6507.95,330.95 J1.7@6540,363
  Signal Layer 2 w10: v1(6356.71,446.76) 6356.71,939.71 6462,1045 v2(6537,1045)
  Bottom Layer w10: R620.1@6295,1045.38 6295,1041.44 6399.44,937 6511,937 6537,963 v2(6537,1045)
HS_TEMP2: J2.7 R626.1 | length 88.8
  Bottom Layer w10: R626.1@6680.62,1085 6687.43,1078.19 6709.81,1078.19 J2.7@6750,1038
HS_ZVS1: C609.1 J1.5 J602.8 | length 1614.6
  Signal Layer 2 w10: J1.5@6490,363 6542,311 6673,311 6965,603 6965,967 6990,992 v1(6991,992)
  Signal Layer 3 w10: v1(6991,992) 6992,991 7098,991 7181,1074 7364.03,1074 J602.8@7450,1159.97
  Bottom Layer w10: J602.8@7450,1151 J602.8@7450,1159 ; J602.8@7450,1159.97 C609.1@7450,1218.38
  Bottom Layer w15: J602.8@7450,1159 J602.8@7450,1159.97
HS_ZVS2: C614.1 J2.5 J602.12 | length 961.1
  Signal Layer 4 w10: J2.5@6800,1038 6889,1127 7617.03,1127 J602.12@7650,1159.97
  Bottom Layer w10: C614.1@7647,1218.38 7648.5,1216.88 7648.5,1161.47 J602.12@7650,1159.97
  Bottom Layer w15: J602.12@7650,1159 J602.12@7650,1159.97
L_Wire: L106.1 pad.1@924,2411 R107.2 R108.2 | length 318.4
  Top Layer w10: pad.1@924,2411 955.44,2442.44 L106.1@1229.41,2442.44
  other v1: 923,2339 796,2340 859,2340 1121,2340 729,2341 987,2341 1047,2341 1229,2379 1292,2379 1143,2386 1143,2435 1292,2443 1047,2481 1116,2481 731,2482 796,2482 859,2482 987,2482 923,2483 1291,2504 1227,2512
